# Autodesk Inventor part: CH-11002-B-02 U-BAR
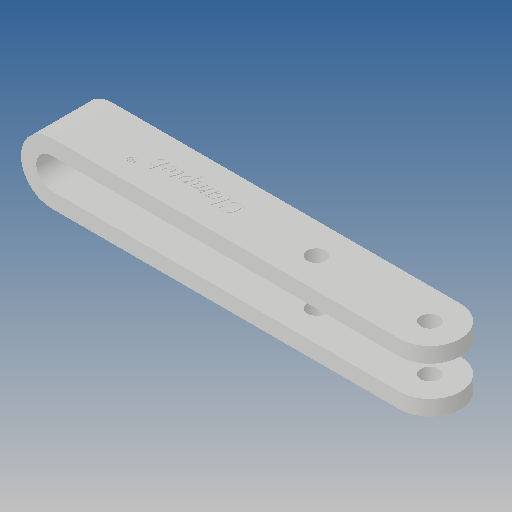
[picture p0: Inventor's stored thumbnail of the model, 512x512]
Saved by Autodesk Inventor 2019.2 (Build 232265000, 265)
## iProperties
Created: 2012-09
Part Number: CH-11002-B-02 U-BAR
Material: Ogólny
Document SubType Name: Modeling
Designer: CADENGINEERING4
Density: 1 g/cm^3
Appearance: Domyślna
Author: CADENGINEERING4
Revision Number: ÈÎºÎ
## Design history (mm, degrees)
feature "ÇÐ³ý-À­Éì5"
node "Bryła1"
